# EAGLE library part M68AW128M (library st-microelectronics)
2 Mbit (128K x16) 3.0V Asynchronous SRAM Source: Source: http://us.st.com/stonline/products/literature/ds/7995.pdf
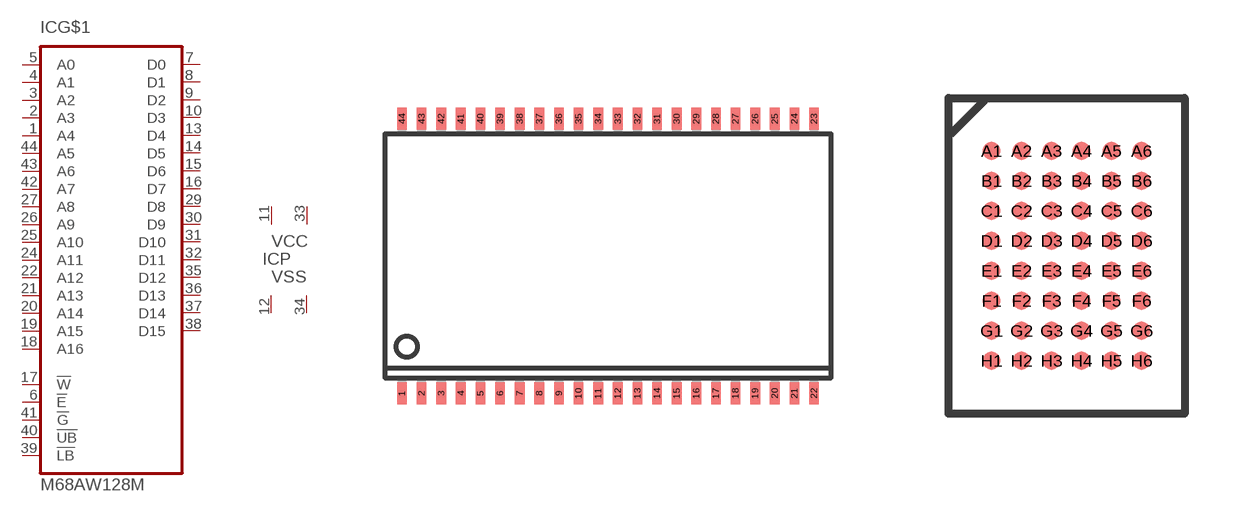
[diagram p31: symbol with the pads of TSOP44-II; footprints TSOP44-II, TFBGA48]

Designator prefix IC; gates G$1=M68AW128M P=VCC2-VSS2

## M68AW128MND (OC_FARNELL: unknown; OC_NEWARK: unknown)  [TSOP44-II]
1  G$1:A4  in
2  G$1:A3  in
3  G$1:A2  in
4  G$1:A1  in
5  G$1:A0  in
6  G$1:!E  in
7  G$1:D0  hiz
8  G$1:D1  hiz
9  G$1:D2  hiz
10  G$1:D3  hiz
11  P:VCC  pwr
12  P:VSS  pwr
13  G$1:D4  hiz
14  G$1:D5  hiz
15  G$1:D6  hiz
16  G$1:D7  hiz
17  G$1:!W  in
18  G$1:A16  in
19  G$1:A15  in
20  G$1:A14  in
21  G$1:A13  in
22  G$1:A12  in
24  G$1:A11  in
25  G$1:A10  in
26  G$1:A9  in
27  G$1:A8  in
29  G$1:D8  hiz
30  G$1:D9  hiz
31  G$1:D10  hiz
32  G$1:D11  hiz
33  P:VCC  pwr
34  P:VSS  pwr
35  G$1:D12  hiz
36  G$1:D13  hiz
37  G$1:D14  hiz
38  G$1:D15  hiz
39  G$1:!LB  in
40  G$1:!UB  in
41  G$1:!G  in
42  G$1:A7  in
43  G$1:A6  in
44  G$1:A5  in

## M68AW128MZB (MPN: M68AW128ML70ZB6; OC_FARNELL: unknown; OC_NEWARK: 37M5198)  [TFBGA48]
A1  G$1:!LB  in
A2  G$1:!G  in
A3  G$1:A0  in
A4  G$1:A1  in
A5  G$1:A2  in
B1  G$1:D8  hiz
B2  G$1:!UB  in
B3  G$1:A3  in
B4  G$1:A4  in
B5  G$1:!E  in
B6  G$1:D0  hiz
C1  G$1:D9  hiz
C2  G$1:D10  hiz
C3  G$1:A5  in
C4  G$1:A6  in
C5  G$1:D1  hiz
C6  G$1:D2  hiz
D1  P:VSS  pwr
D2  G$1:D11  hiz
D4  G$1:A7  in
D5  G$1:D3  hiz
D6  P:VCC  pwr
E1  P:VCC  pwr
E2  G$1:D12  hiz
E4  G$1:A16  in
E5  G$1:D4  hiz
E6  P:VSS  pwr
F1  G$1:D14  hiz
F2  G$1:D13  hiz
F3  G$1:A14  in
F4  G$1:A15  in
F5  G$1:D5  hiz
F6  G$1:D6  hiz
G1  G$1:D15  hiz
G3  G$1:A12  in
G4  G$1:A13  in
G5  G$1:!W  in
G6  G$1:D7  hiz
H2  G$1:A8  in
H3  G$1:A9  in
H4  G$1:A10  in
H5  G$1:A11  in

## Footprint TSOP44-II (pad centres in mm)
44 lead Plastic Thin Small Outline Type II Source: http://us.st.com/stonline/products/literature/ds/7995.pdf
smd 0.4 x 0.9: 1 -8.4,-5.6; 2 -7.6,-5.6; 3 -6.8,-5.6; 4 -6,-5.6; 5 -5.2,-5.6; 6 -4.4,-5.6; 7 -3.6,-5.6; 8 -2.8,-5.6; 9 -2,-5.6; 10 -1.2,-5.6; 11 -0.4,-5.6; 12 0.4,-5.6; 13 1.2,-5.6; 14 2,-5.6; 15 2.8,-5.6; 16 3.6,-5.6; 17 4.4,-5.6; 18 5.2,-5.6; 19 6,-5.6; 20 6.8,-5.6; 21 7.6,-5.6; 22 8.4,-5.6; 23 8.4,5.6; 24 7.6,5.6; 25 6.8,5.6; 26 6,5.6; 27 5.2,5.6; 28 4.4,5.6; 29 3.6,5.6; 30 2.8,5.6; 31 2,5.6; 32 1.2,5.6; 33 0.4,5.6; 34 -0.4,5.6; 35 -1.2,5.6; 36 -2,5.6; 37 -2.8,5.6; 38 -3.6,5.6; 39 -4.4,5.6; 40 -5.2,5.6; 41 -6,5.6; 42 -6.8,5.6; 43 -7.6,5.6; 44 -8.4,5.6

## Footprint TFBGA48 (pad centres in mm)
TFBGA48 6x8mm - 6x8 Active Ball Array, 0.75mm pitch Source: http://us.st.com/stonline/products/literature/ds/7995.pdf
smd 0.45 x 0.45: A1 -1.875,2.625; A2 -1.125,2.625; A3 -0.375,2.625; A4 0.375,2.625; A5 1.125,2.625; A6 1.875,2.625; B1 -1.875,1.875; B2 -1.125,1.875; B3 -0.375,1.875; B4 0.375,1.875; B5 1.125,1.875; B6 1.875,1.875; C1 -1.875,1.125; C2 -1.125,1.125; C3 -0.375,1.125; C4 0.375,1.125; C5 1.125,1.125; C6 1.875,1.125; D1 -1.875,0.375; D2 -1.125,0.375; D3 -0.375,0.375; D4 0.375,0.375; D5 1.125,0.375; D6 1.875,0.375; E1 -1.875,-0.375; E2 -1.125,-0.375; E3 -0.375,-0.375; E4 0.375,-0.375; E5 1.125,-0.375; E6 1.875,-0.375; F1 -1.875,-1.125; F2 -1.125,-1.125; F3 -0.375,-1.125; F4 0.375,-1.125; F5 1.125,-1.125; F6 1.875,-1.125; G1 -1.875,-1.875; G2 -1.125,-1.875; G3 -0.375,-1.875; G4 0.375,-1.875; G5 1.125,-1.875; G6 1.875,-1.875; H1 -1.875,-2.625; H2 -1.125,-2.625; H3 -0.375,-2.625; H4 0.375,-2.625; H5 1.125,-2.625; H6 1.875,-2.625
